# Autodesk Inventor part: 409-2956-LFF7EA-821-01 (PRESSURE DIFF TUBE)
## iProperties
Created: 2010-09
Part Number: 409-2956-LFF7EA-821-01 (PRESSURE DIFF TUBE)
Material: 3/8" OD TUBE - SS
Document SubType Name: Modeling
Designer: S. Boerckel
Engineer: Steve Boerckel
Mass: 15.0126 g
Surface Area: 31.4303 cm^2
Volume: 1.85799 cm^3
Density: 8.08 g/cm^3
Description: PT TUBE
LGTH: 6.977 in
Author: S. Boerckel
Revision Number: 0
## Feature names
1. Sweep2
